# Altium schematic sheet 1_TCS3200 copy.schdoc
size 497 x 243 mm
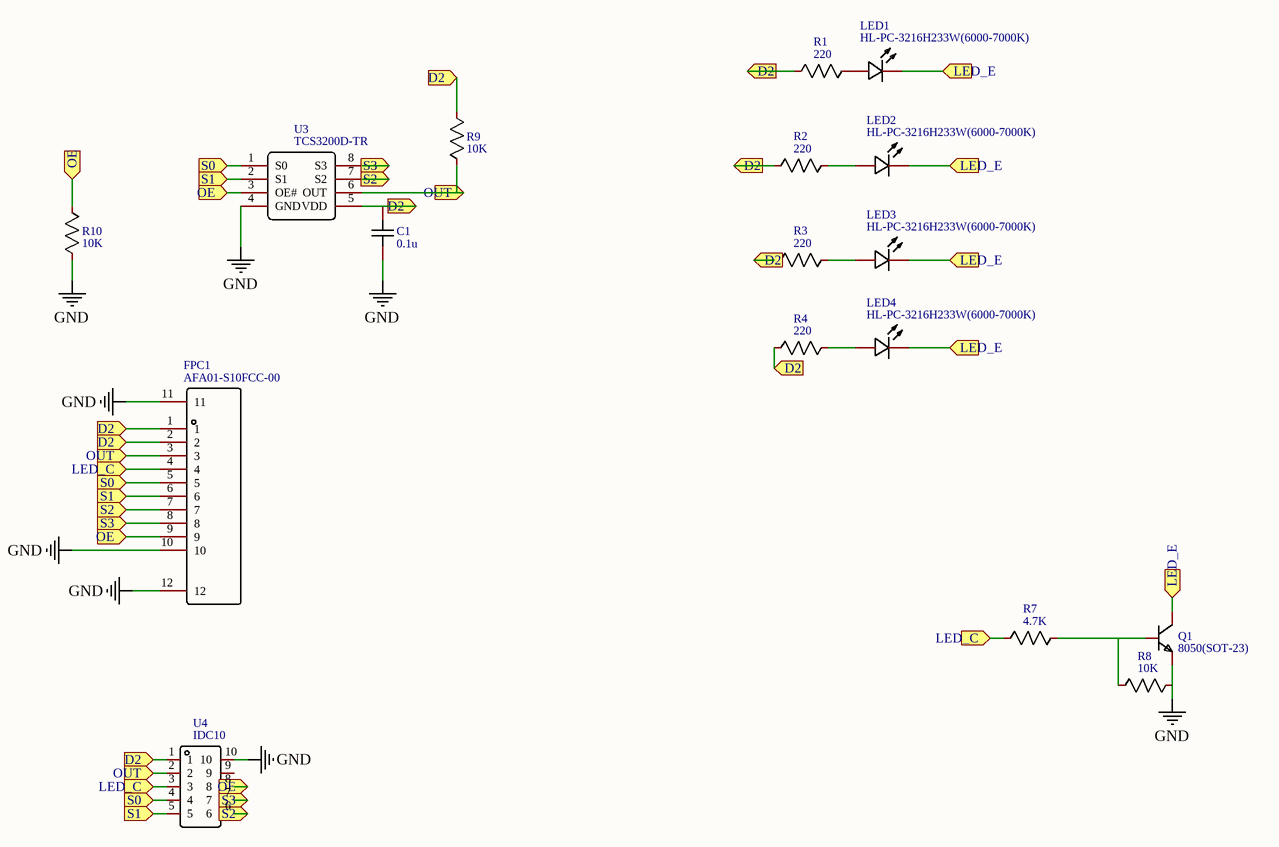
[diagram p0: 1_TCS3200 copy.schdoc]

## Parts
C1  0.1u  [C0805]
FPC1  AFA01-S10FCC-00  [FPC-SMD_AFA01-S10FCC-00]
LED1  HL-PC-3216H233W(6000-7000K)
LED2  HL-PC-3216H233W(6000-7000K)
LED3  HL-PC-3216H233W(6000-7000K)
LED4  HL-PC-3216H233W(6000-7000K)
Q1  Name: 8050(SOT-23)  (hidden comment: 2n3904S-RTK/PS)
R1  220
R2  220
R3  220
R4  220
R7  4.7K
R8  10K
R9  10K
R10  10K
U3  TCS3200D-TR
U4  IDC10

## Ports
D2 (in), LED_C (in), LED_E (in), OE (in), OUT (in), S0 (in), S1 (in), S2 (in), S3 (in)

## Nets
GND: C1.1 FPC1.10 FPC1.11 FPC1.12 Q1.1(E) R8.2 R10.1 U3.4(GND) U4.10
D2: C1.2 FPC1.1 FPC1.2 R1.1 R2.1 R3.1 R4.1 R9.2 U3.5(VDD) U4.1 ; port D2
LED_C: FPC1.4 R7.1 U4.3 ; port LED_C
LED_E: LED1.2(C) LED2.2(C) LED3.2(C) LED4.2(C) Q1.3(C) ; port LED_E
OE: FPC1.9 R10.2 U3.3(OE#) U4.8 ; port OE
OUT: FPC1.3 R9.1 U3.6(OUT) U4.2 ; port OUT
S0: FPC1.5 U3.1(S0) U4.4 ; port S0
S1: FPC1.6 U3.2(S1) U4.5 ; port S1
S2: FPC1.7 U3.7(S2) U4.6 ; port S2
S3: FPC1.8 U3.8(S3) U4.7 ; port S3
NetLED1_1: LED1.1(A) R1.2
NetLED2_1: LED2.1(A) R2.2
NetLED3_1: LED3.1(A) R3.2
NetLED4_1: LED4.1(A) R4.2
NetQ1_2: Q1.2(B) R7.2 R8.1

Not connected (* = marked no-connect by the designer): U4 9

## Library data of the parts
C1 = 0.1u: Convert to PCB: yes
FPC1 = AFA01-S10FCC-00: Manufacturer: JUSHUO; Convert to PCB: yes
LED1-LED4 = HL-PC-3216H233W(6000-7000K): Manufacturer: Hongli Zhihui (HONGLITRONIC); Convert to PCB: yes; Origin Footprint: LED1206-R-RD_WHITE
Q1 = 2n3904S-RTK/PS: Manufacturer: KEC; Paste Type: SOT-23; Convert to PCB: yes; Origin Footprint: SOT-23-3_L2.9-W1.3-P1.90-LS2.4-TR
R1-R4 = 220: Convert to PCB: yes; Origin Footprint: R0805
R7 = 4.7K: Convert to PCB: yes; Origin Footprint: R0805
R8-R10 = 10K: Convert to PCB: yes; Origin Footprint: R0805
U3 = TCS3200D-TR: Manufacturer: Ams; Convert to PCB: yes; Origin Footprint: SOIC-8_L4.9-W3.9-P1.27-LS6.0-BL
U4 = IDC10: Manufacturer: null; Convert to PCB: yes; Origin Footprint: HDR-TH_10P-P2.54-V-M-R2-C5-S2.54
